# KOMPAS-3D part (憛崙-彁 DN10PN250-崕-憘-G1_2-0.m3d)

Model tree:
1. Объединить компоненты:1  (labels: СЕНС-ПР DN10PN250-НО-G1/2-0)
2. Эскиз:1
3. Операция выдавливания:1
     Расстояние 1 = 14
4. Фаска:1
     Угол = 45; Длина 1 = 2; Длина 2 = 2

Referenced files in D:\Савин\!СЕНСОР\3D для заказчика\!Новый перечень\СЕНС-ПР\6. СЕНС-ПР-PN250-НО\DN10\: СЕНС-ПР DN10PN250-НО-G1_2-0.a3d
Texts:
  СЕНС-ПР DN10PN250-НО-СВ-G1/2-0
  ООО НПП Сенсор
  СЕНС-ПР DN10PN250-НО-G1/2-0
